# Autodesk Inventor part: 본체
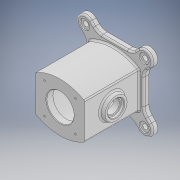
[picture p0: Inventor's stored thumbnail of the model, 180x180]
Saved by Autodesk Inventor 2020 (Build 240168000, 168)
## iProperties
Created: 2022-01
Part Number: 본체
Material: 일반
Document SubType Name: Modeling
Designer: user
Density: 1 g/cm^3
Appearance: 기본값
Author: user
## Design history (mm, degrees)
sketch "스케치1"
  geometry: L1 (53, -53)-(31.787, -53); L2 (-53, -53)-(-53, -31.787); L3 (-53, 53)-(-31.787, 53); L4 (53, 53)-(53, 31.787); L5 (53, -53)-(-53, 53); L6 (-53, -53)-(53, 53); L7 (0, 0)-(54.447, 54.447); L8 (53, 31.787)-(65.054, 43.841); L9 (65.054, 43.841)-(43.841, 65.054); L10 (43.841, 65.054)-(31.787, 53); L11 (0, 77)-(0, 0); L12 (-53, 0)-(53, 0); L13 (65.054, -43.841)-(43.841, -65.054); L14 (43.841, -65.054)-(31.787, -53); L15 (53, -31.787)-(65.054, -43.841); L16 (-53, 31.787)-(-65.054, 43.841); L17 (-43.841, 65.054)-(-31.787, 53); L18 (-65.054, 43.841)-(-43.841, 65.054); L19 (-53, -31.787)-(-65.054, -43.841); L20 (-53, 53)-(-53, -53); L21 (-43.841, -65.054)-(-31.787, -53); L22 (-65.054, -43.841)-(-43.841, -65.054); L23 (-31.787, 53)-(31.787, 53); L24 (-53, 31.787)-(-53, 53); L25 (-53, -31.787)-(-53, 31.787); L26 (-31.787, -53)-(-53, -53); L27 (31.787, -53)-(-31.787, -53); L28 (53, -31.787)-(53, -53); L29 (53, 31.787)-(53, -31.787); L30 (31.787, 53)-(53, 53); A1 r 77 centre (0, 0) between (54.447, 54.447) and (0, 77); A2 r 15 centre (54.447, 54.447) between (65.054, 43.841) and (43.841, 65.054); A3 r 15 centre (54.447, -54.447) between (43.841, -65.054) and (65.054, -43.841); A4 r 15 centre (-54.447, 54.447) between (-43.841, 65.054) and (-65.054, 43.841); A5 r 15 centre (-54.447, -54.447) between (-65.054, -43.841) and (-43.841, -65.054); 4 further points
  constraints: 60 end point, 20 parallel, 18 symmetric about line, 10 perpendicular, 10 point on circle, 5 centre point, 5 coincident, 3 horizontal, 3 midpoint, 3 point on line, 1 tangent, 1 vertical, 3 other
  dimensions: "d0" = 106 distance of L3.start L4.start; "d1" = 106 distance of L2.start L3.start; "d2" = 154 diameter of A1; "d3" = 30 distance of L9.end L8.end
extrude "돌출1" new body sketch "스케치1" distance "d5" = 10; taper "d6" = 0 deg
fillet "모깎기1" dims "d7" = 20
sketch "스케치2"
  geometry: L1 (-45, -45)-(45, -45); L2 (45, -45)-(45, -32.942); L3 (45, 45)-(-45, 45); L4 (-45, 45)-(-45, 32.942); L5 (-45, -45)-(45, 45); L6 (45, -45)-(-45, 45); L7 (23.503, 53)-(-23.503, 53) reference; L8 (0, 53)-(0, -102.759); L9 (-23.503, -53)-(23.503, -53) reference; L10 (0, -53)-(0, 133.389); L11 (45, 32.942)-(45, 45); L12 (45, -32.942)-(45, 32.942); L13 (-45, -32.942)-(-45, -45); L14 (-45, 32.942)-(-45, -32.942); A1 r 90 centre (0, -45) between (45, 32.942) and (-45, 32.942); A2 r 90 centre (0, 45) between (-45, -32.942) and (45, -32.942); 1 further point
  constraints: 24 end point, 10 parallel, 6 point on circle, 5 midpoint, 4 point on line, 3 perpendicular, 2 centre point, 1 horizontal, 1 vertical
  dimensions: "d8" = 90 distance of L3.end L3.start; "d9" = 90 distance of L3.start L1.end; "d10" = 180 diameter of A1
extrude "돌출2" join sketch "스케치2" distance "d11" = 100; taper "d12" = 0 deg
sketch "스케치3"
  geometry: L1 (10, 32.942)-(-100, 32.942); L2 (-100, 65.885)-(-100, 0) reference; L3 (10, 9.44)-(10, 56.445) reference; C1 r 20 at (-50, 32.942)
  constraints: 2 end point, 1 centre point, 1 midpoint, 1 point on line
  dimensions: "d13" = 40 diameter of C1; "d14" = 60 distance from line of L3 C1.centre
extrude "돌출3" join sketch "스케치3" distance "d15" = 8; taper "d16" = 0 deg
feature "면 기울기1" dims angle "d17" = 15 deg
sketch "스케치4"
  geometry: A1 r 15 centre (-54.447, 54.447) between (-43.841, 65.054) and (-65.054, 43.841) reference; A2 r 15 centre (54.447, 54.447) between (65.054, 43.841) and (43.841, 65.054) reference; A3 r 15 centre (54.447, -54.447) between (43.841, -65.054) and (65.054, -43.841) reference; A4 r 15 centre (-54.447, -54.447) between (-65.054, -43.841) and (-43.841, -65.054) reference; 5 further points
  constraints: 4 coincident
hole "구멍1" sketch "스케치4" at (-54.447, 54.447), (54.447, 54.447), (54.447, -54.447), (-54.447, -54.447) diameter "d18" = 9; stored, may be unused: countersink angle "d22" = 90 deg, drill point angle "d24" = 0 deg; dims "d19" = 8, "d20" = 18, "d21" = 2, "d23" = 10
sketch "스케치5"
  geometry: L1 (-54.447, 54.447)-(54.447, -54.447); L2 (54.447, -54.447)-(-54.447, -54.447); L3 (-54.447, -54.447)-(54.447, 54.447); C1 r 4.5 at (-54.447, 54.447) reference; C2 r 4.5 at (54.447, -54.447) reference; C3 r 4.5 at (-54.447, -54.447) reference; A1 r 40 centre (0, 0) between (-28.284, 28.284) and (-28.284, -28.284); A2 r 15 centre (54.447, 54.447) between (65.054, 43.841) and (43.841, 65.054) reference; 3 further points
  constraints: 6 end point, 4 point on circle, 4 point on line, 1 centre point, 1 coincident, 1 horizontal, 1 perpendicular
  dimensions: "d25" = 80 diameter of A1
hole "구멍2" sketch "스케치5" at (-28.284, 28.284), (-28.284, -28.284), (28.284, -28.284), (28.284, 28.284) diameter "d26" = 3.242; stored, may be unused: countersink angle "d30" = 90 deg, drill point angle "d32" = 118 deg; dims "d27" = 8, "d28" = 18, "d29" = 2, "d31" = 10
sketch "스케치6"
  geometry: C1 r 25 at (0, 0); 1 further point
  constraints: 1 centre point, 1 coincident
  dimensions: "d33" = 50 diameter of C1
extrude "돌출4" cut sketch "스케치6" distance "d34" = 12; taper "d35" = 0 deg
sketch "스케치7"
  geometry: C1 r 37 at (0, 0); 1 further point
  constraints: 1 centre point, 1 coincident
  dimensions: "d36" = 74 diameter of C1
extrude "돌출5" cut sketch "스케치7" distance "d37" = 86; taper "d38" = 0 deg
sketch "스케치8"
  geometry: C1 r 25 at (0, 0); 1 further point
  constraints: 1 centre point, 1 coincident
  dimensions: "d39" = 50 diameter of C1
extrude "돌출6" cut sketch "스케치8" distance "d40" = 12; taper "d41" = 0 deg
sketch "스케치9"
  geometry: C1 r 20 at (0, 0) reference; 2 further points
  constraints: 1 coincident
hole "구멍3" sketch "스케치9" at (0, 0) diameter "d42" = 24; stored, may be unused: countersink angle "d46" = 90 deg, drill point angle "d48" = 0 deg; dims "d43" = 8, "d44" = 30, "d45" = 5, "d47" = 10
chamfer "모따기1" distance "d49" = 1; stored, may be unused: second distance "d50" = 2, angle "d51" = 45 deg
fillet "모깎기2" dims "d52" = 3
fillet "모깎기3" dims "d53" = 3
fillet "모깎기4" dims "d54" = 3
fillet "모깎기5" dims "d55" = 3
chamfer "모따기2" distance "d56" = 1; stored, may be unused: second distance "d57" = 2, angle "d58" = 45 deg
fillet "모깎기6" dims "d59" = 3
node "작업 평면1"
sketch "스케치10"
  geometry: L1 (-26, 0)-(26, 0) reference; L2 (53, 44)-(53, 76) reference; 2 further points
  constraints: 1 other
  dimensions: "d61" = 60 distance from line of L1 point (0, 60); "d62" = 53 distance from line of point (0, 60) L2
feature "엠보싱1" sketch "스케치10" dims "d63" = 0.5, "d64" = 0
sketch "스케치11" dims "d65" = 80
  geometry: L1 (54.447, 54.447)-(-54.447, -54.447); L2 (-54.447, 54.447)-(54.447, -54.447); C1 r 4.5 at (54.447, 54.447) reference; C2 r 4.5 at (-54.447, -54.447) reference; C3 r 9 at (-54.447, 54.447) reference; C4 r 4.5 at (54.447, -54.447) reference; C5 r 1.621 at (28.284, 28.284) reference; C6 r 1.621 at (28.284, -28.284) reference; C7 r 1.621 at (-28.284, -28.284) reference; 6 further points
  constraints: 4 coincident, 4 end point, 1 point on line, 3 other
hole "구멍4" sketch "스케치11" at (28.284, 28.284), (28.284, -28.284), (-28.284, -28.284), (-28.284, 28.284) diameter "d66" = 3.242; stored, may be unused: countersink angle "d70" = 90 deg, drill point angle "d72" = 118 deg; dims "d67" = 8, "d68" = 30, "d69" = 5, "d71" = 10
node "솔리드1"
feature "A9D066F2-1C7D-4E18-AEED-F7BC21143FA4" dims "d18" = 9, "d19" = 8, "d20" = 18, "d21" = 2, "d22" = 90 deg, "d23" = 10, "d24" = 0
other parameters: "d60" = 0
